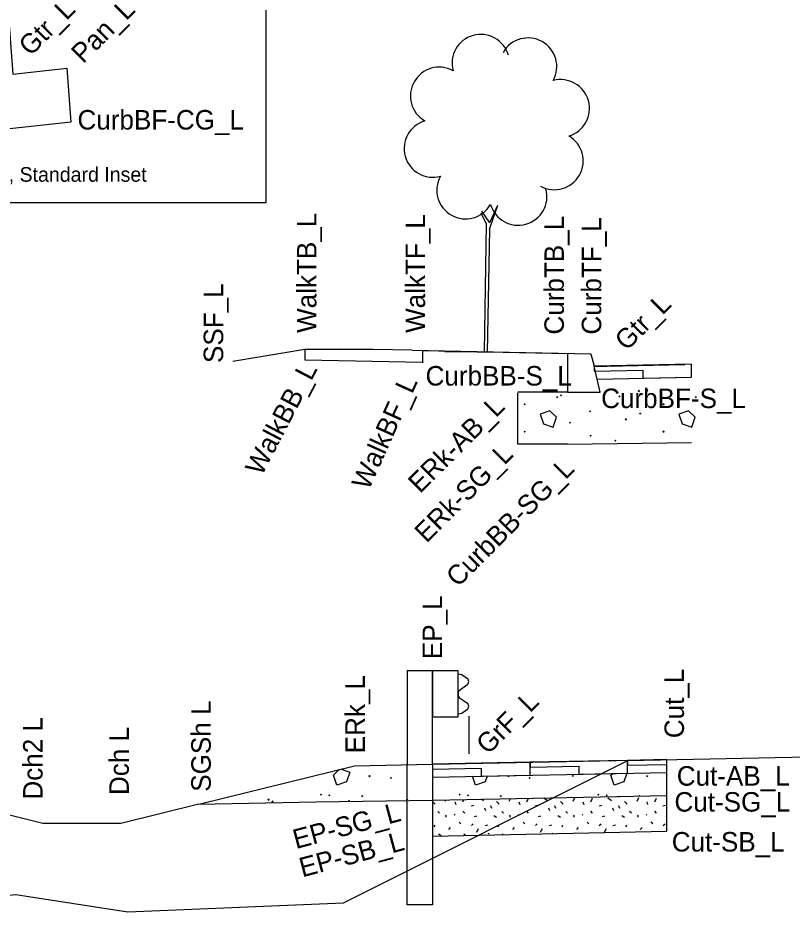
# Model space of a CAD drawing. Extents: x 0 to 1.42, y 0 to 0.92.
# Drawn here: x 0.3094 to 0.6404, y 0.3166 to 0.7008 of the extents above; entities that cross this region are included whole.
import ezdxf

# ---------------------------------------------------------------- set-up
doc = ezdxf.new("R2010")
doc.units = 0
for name, color, linetype in [('E_LDSC_VEG_Deciduous', 7, 'Continuous'), ('Level 14', 7, 'Continuous'), ('Level 63', 7, 'Continuous'), ('P_RDWY_PLAN_Detail', 7, 'Continuous'), ('P_RDWY_PLAN_DetailTx', 7, 'Continuous'), ('S_PROP_ROW', 7, 'Continuous')]:
    doc.layers.add(name, color=color, linetype=linetype)

msp = doc.modelspace()

# ---------------------------------------------------------------- linework, layer by layer
at = {"layer": 'E_LDSC_VEG_Deciduous'}
for centre, radius, start, end in [((0.5072960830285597, 0.6814221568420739), 0.012303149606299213, 16.313852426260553, 195.03894938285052), ((0.5274965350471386, 0.6799151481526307), 0.012303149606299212, 331.3138524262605, 150.03894938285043), ((0.4895086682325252, 0.667436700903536), 0.012303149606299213, 61.31385242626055, 240.03894938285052), ((0.5414819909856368, 0.6621277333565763), 0.012303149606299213, 286.3138524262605, 105.03894938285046), ((0.4868202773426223, 0.6449698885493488), 0.012303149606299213, 106.31385242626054, 285.0389493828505), ((0.5387936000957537, 0.639660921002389), 0.012303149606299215, 241.31385242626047, 60.03894938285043), ((0.5008057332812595, 0.6271824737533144), 0.01230314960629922, 151.31385242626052, 330.0389493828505), ((0.5232725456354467, 0.6244940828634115), 0.012303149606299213, 196.31385242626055, 15.038949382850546)]:
    msp.add_arc(centre, radius, start, end, dxfattribs=at)
at = {"layer": 'Level 14'}
for p, q in [((0.4977306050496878, 0.4204527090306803), (0.4991851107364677, 0.4201957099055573)), ((0.4991851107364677, 0.4201957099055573), (0.5013778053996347, 0.41865918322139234)), ((0.4979930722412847, 0.4134262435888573), (0.5013778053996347, 0.41579391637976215)), ((0.4976212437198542, 0.4127044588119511), (0.4976212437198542, 0.41114059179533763)), ((0.4979930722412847, 0.4104188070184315), (0.5013778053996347, 0.40805113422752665)), ((0.4977306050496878, 0.4033923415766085), (0.4991851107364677, 0.40364934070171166)), ((0.4991851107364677, 0.40364934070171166), (0.5013778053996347, 0.40518586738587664))]:
    msp.add_line(p, q, dxfattribs=at)
for points in [[(0.4866851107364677, 0.3818481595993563), (0.4866851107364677, 0.4217650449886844), (0.47574897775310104, 0.4217650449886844), (0.47574897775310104, 0.3818481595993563)], [(0.4866851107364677, 0.3818481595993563), (0.4866851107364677, 0.3216994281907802), (0.47574897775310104, 0.3216994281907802), (0.47574897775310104, 0.3818481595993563)]]:
    msp.add_lwpolyline(points, dxfattribs=at)
msp.add_lwpolyline([(0.4976212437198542, 0.4217650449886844), (0.4866851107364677, 0.4217650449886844), (0.4866851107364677, 0.4020800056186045), (0.4976212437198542, 0.4020800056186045)], close=True, dxfattribs=at)
for centre, radius, start, end in [((0.5003762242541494, 0.41722560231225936), 0.0017497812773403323, 304.9992805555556, 55.00071666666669), ((0.4984960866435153, 0.41270705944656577), 0.0008748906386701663, 125.01187222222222, 180), ((0.4984960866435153, 0.4111379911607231), 0.0008748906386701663, 180, 234.98812777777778), ((0.5003762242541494, 0.4066194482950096), 0.0017497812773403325, 304.9992833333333, 55.00071944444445)]:
    msp.add_arc(centre, radius, start, end, dxfattribs=at)
at = {"layer": 'Level 63'}
msp.add_lwpolyline([(0.41534290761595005, 0.6217266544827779), (0.2093492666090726, 0.6217266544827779), (0.2093492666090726, 0.7221789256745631), (0.41534290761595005, 0.7221789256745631)], close=True, dxfattribs=at)
at = {"layer": 'P_RDWY_PLAN_Detail'}
for p, q in [((0.5143879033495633, 0.6206599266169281), (0.5109247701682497, 0.6104224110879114)), ((0.5143879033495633, 0.6206599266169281), (0.5109945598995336, 0.613146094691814)), ((0.507298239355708, 0.6175089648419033), (0.5096245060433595, 0.6128309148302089)), ((0.5076012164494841, 0.6182361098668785), (0.5109945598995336, 0.613146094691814)), ((0.5096245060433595, 0.6128309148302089), (0.5087280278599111, 0.558145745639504)), ((0.510951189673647, 0.6105005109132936), (0.5100902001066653, 0.5579801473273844)), ((0.48256132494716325, 0.5533570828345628), (0.48256132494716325, 0.5583822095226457)), ((0.4918710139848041, 0.5581643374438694), (0.5195385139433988, 0.5578846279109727)), ((0.578683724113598, 0.541876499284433), (0.5782191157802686, 0.5414118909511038)), ((0.5782191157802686, 0.541876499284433), (0.578683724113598, 0.5414118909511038)), ((0.5443556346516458, 0.5408064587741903), (0.5231866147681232, 0.5408932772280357)), ((0.5231866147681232, 0.5186843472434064), (0.5231866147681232, 0.5405687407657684)), ((0.5401213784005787, 0.5389331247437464), (0.5396567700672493, 0.5384685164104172)), ((0.5396567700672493, 0.5389331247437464), (0.5401213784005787, 0.5384685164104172)), ((0.5418249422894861, 0.5397083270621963), (0.5413603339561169, 0.5392437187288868)), ((0.5413603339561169, 0.5397083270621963), (0.5418249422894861, 0.5392437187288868)), ((0.5611830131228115, 0.5412570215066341), (0.560719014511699, 0.5407924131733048)), ((0.560719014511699, 0.5412570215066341), (0.5611830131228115, 0.5407924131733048)), ((0.5667583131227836, 0.5392428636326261), (0.5662937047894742, 0.5387782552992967)), ((0.5662937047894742, 0.5392428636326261), (0.5667583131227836, 0.5387782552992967)), ((0.5751212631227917, 0.5415667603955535), (0.5746566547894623, 0.5411021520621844)), ((0.5746566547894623, 0.5415667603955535), (0.5751212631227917, 0.5411021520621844)), ((0.5994362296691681, 0.5389331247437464), (0.5989716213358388, 0.5384685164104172)), ((0.5989716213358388, 0.5389331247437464), (0.5994362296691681, 0.5384685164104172)), ((0.5263379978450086, 0.5358357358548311), (0.5258733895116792, 0.5353711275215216)), ((0.5258733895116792, 0.5358357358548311), (0.5263379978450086, 0.5353711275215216)), ((0.585652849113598, 0.5358357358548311), (0.5851882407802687, 0.5353711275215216)), ((0.5851882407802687, 0.5358357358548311), (0.585652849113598, 0.5353711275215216)), ((0.5542144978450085, 0.5328932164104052), (0.553749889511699, 0.5324286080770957)), ((0.553749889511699, 0.5328932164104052), (0.5542144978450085, 0.5324286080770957)), ((0.5755863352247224, 0.5319639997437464), (0.5751217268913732, 0.5314993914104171)), ((0.5751217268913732, 0.5319639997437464), (0.5755863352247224, 0.5314993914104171)), ((0.5456966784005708, 0.528092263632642), (0.5452320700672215, 0.5276276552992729)), ((0.5452320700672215, 0.528092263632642), (0.5456966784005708, 0.5276276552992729)), ((0.5695459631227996, 0.5294860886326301), (0.5690813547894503, 0.5290214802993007)), ((0.5690813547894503, 0.5294860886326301), (0.5695459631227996, 0.5290214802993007)), ((0.5263379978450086, 0.5242205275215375), (0.5258733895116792, 0.5237559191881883)), ((0.5258733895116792, 0.5242205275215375), (0.5263379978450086, 0.5237559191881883)), ((0.5545242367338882, 0.5225169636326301), (0.5540596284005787, 0.5220523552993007)), ((0.5540596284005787, 0.5225169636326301), (0.5545242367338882, 0.5220523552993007)), ((0.585652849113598, 0.5242205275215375), (0.5851882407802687, 0.5237559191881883)), ((0.5851882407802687, 0.5242205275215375), (0.585652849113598, 0.5237559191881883)), ((0.5443556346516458, 0.5185975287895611), (0.5231866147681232, 0.5186843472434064)), ((0.565054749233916, 0.5203487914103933), (0.5645901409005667, 0.5198841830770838)), ((0.5645901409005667, 0.5203487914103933), (0.565054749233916, 0.5198841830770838)), ((0.5021260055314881, 0.40245278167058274), (0.5021260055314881, 0.38632364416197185)), ((0.4594806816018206, 0.37697243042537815), (0.45994528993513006, 0.37650782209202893)), ((0.45994528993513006, 0.37697243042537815), (0.4594806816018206, 0.37650782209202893)), ((0.5187955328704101, 0.37697243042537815), (0.5192601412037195, 0.37650782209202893)), ((0.5192601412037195, 0.37697243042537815), (0.5187955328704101, 0.37650782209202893)), ((0.5463622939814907, 0.37712729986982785), (0.5468269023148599, 0.37666269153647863)), ((0.5468269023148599, 0.37712729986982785), (0.5463622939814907, 0.37666269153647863)), ((0.5781103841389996, 0.37697243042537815), (0.5785749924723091, 0.37650782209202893)), ((0.5785749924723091, 0.37697243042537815), (0.5781103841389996, 0.37650782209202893)), ((0.46861797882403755, 0.3761980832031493), (0.46908258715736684, 0.3757334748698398)), ((0.46908258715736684, 0.3761980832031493), (0.46861797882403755, 0.3757334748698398)), ((0.527932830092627, 0.3761980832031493), (0.5283974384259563, 0.3757334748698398)), ((0.5283974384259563, 0.3761980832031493), (0.527932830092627, 0.3757334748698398)), ((0.43872832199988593, 0.36907408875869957), (0.4391929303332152, 0.36860948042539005)), ((0.4391929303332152, 0.36907408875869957), (0.43872832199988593, 0.36860948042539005)), ((0.49804317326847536, 0.36907408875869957), (0.49850778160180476, 0.36860948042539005)), ((0.49850778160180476, 0.36907408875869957), (0.49804317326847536, 0.36860948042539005)), ((0.5573580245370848, 0.36907408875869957), (0.5578226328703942, 0.36860948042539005)), ((0.5578226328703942, 0.36907408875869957), (0.5573580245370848, 0.36860948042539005)), ((0.39135542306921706, 0.3659923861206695), (0.39133888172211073, 0.3659758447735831)), ((0.3917020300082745, 0.36607730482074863), (0.3918034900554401, 0.3659758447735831)), ((0.4162722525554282, 0.36690591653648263), (0.4167368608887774, 0.3664413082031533)), ((0.4167368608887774, 0.36690591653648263), (0.4162722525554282, 0.3664413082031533)), ((0.4179758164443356, 0.3661307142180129), (0.4184404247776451, 0.36566610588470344)), ((0.4184404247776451, 0.3661307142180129), (0.4179758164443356, 0.36566610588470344)), ((0.4422907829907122, 0.36876434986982), (0.44275539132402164, 0.3682997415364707)), ((0.44275539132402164, 0.36876434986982), (0.4422907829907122, 0.3682997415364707)), ((0.4506537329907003, 0.3664404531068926), (0.45106603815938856, 0.36602814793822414)), ((0.45111834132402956, 0.3664404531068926), (0.4506993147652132, 0.366021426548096)), ((0.4562290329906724, 0.36845461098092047), (0.4566930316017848, 0.3679900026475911)), ((0.4566930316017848, 0.36845461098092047), (0.4562290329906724, 0.3679900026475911)), ((0.4755871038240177, 0.36690591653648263), (0.47600773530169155, 0.36648528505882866)), ((0.4760517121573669, 0.36690591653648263), (0.47562404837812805, 0.3664782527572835)), ((0.5016056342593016, 0.36876434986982), (0.5020702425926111, 0.3682997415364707)), ((0.5020702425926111, 0.36876434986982), (0.5016056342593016, 0.3682997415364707)), ((0.5155438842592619, 0.36845461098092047), (0.5160078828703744, 0.3679900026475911)), ((0.5160078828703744, 0.36845461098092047), (0.5155438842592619, 0.3679900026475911)), ((0.5609204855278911, 0.36876434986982), (0.5613850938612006, 0.3682997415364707)), ((0.5613850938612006, 0.36876434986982), (0.5609204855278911, 0.3682997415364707)), ((0.5748587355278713, 0.36845461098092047), (0.5750132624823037, 0.3682998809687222)), ((0.5753227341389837, 0.36845461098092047), (0.5751710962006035, 0.3683027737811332))]:
    msp.add_line(p, q, dxfattribs=at)
for points in [[(0.2965892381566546, 0.6999072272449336), (0.3054267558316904, 0.6996089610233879), (0.3071230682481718, 0.6767087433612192), (0.33023510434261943, 0.6793088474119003), (0.33193930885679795, 0.6563020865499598), (0.2965892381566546, 0.6523252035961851)], [(0.5974048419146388, 0.5528064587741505), (0.555738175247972, 0.5519731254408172), (0.555738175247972, 0.5498889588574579), (0.5765715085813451, 0.5503056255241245), (0.5765715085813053, 0.5468897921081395), (0.5974048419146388, 0.5473064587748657)], [(0.5382629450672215, 0.5259240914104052), (0.5396567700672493, 0.530105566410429), (0.5368691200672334, 0.5328932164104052), (0.5326876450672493, 0.5314993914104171), (0.5340814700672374, 0.5273179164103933)], [(0.597577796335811, 0.5259240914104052), (0.5989716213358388, 0.530105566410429), (0.5961839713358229, 0.5328932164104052), (0.5920024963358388, 0.5314993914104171), (0.5933963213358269, 0.5273179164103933)], [(0.5283517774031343, 0.38268149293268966), (0.4866851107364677, 0.3818481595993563), (0.4866851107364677, 0.37976399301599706), (0.5075184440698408, 0.38018065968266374), (0.5075184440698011, 0.3767648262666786), (0.5283517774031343, 0.3771814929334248)], [(0.5700184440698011, 0.38351482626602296), (0.5283517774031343, 0.38268149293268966), (0.5283517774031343, 0.3805973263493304), (0.5491851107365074, 0.38101399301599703), (0.5491851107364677, 0.377598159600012), (0.5700184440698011, 0.37801482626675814)], [(0.5868895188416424, 0.3838522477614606), (0.5700184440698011, 0.38351482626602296), (0.5700184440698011, 0.38143065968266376), (0.5868895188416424, 0.38176808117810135)]]:
    msp.add_lwpolyline(points, close=True, dxfattribs=at)
for points in [[(0.4320959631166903, 0.5591381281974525), (0.40128841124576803, 0.554003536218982)], [(0.4779880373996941, 0.5588047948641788), (0.4613213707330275, 0.5591381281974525), (0.4320061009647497, 0.5591381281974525)], [(0.4320959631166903, 0.5591381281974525), (0.4320061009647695, 0.5546450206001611), (0.48256132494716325, 0.5536339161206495)], [(0.4506020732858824, 0.5591113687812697), (0.447226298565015, 0.5591788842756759)], [(0.4779880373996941, 0.5588047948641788), (0.5544048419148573, 0.5571664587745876), (0.555738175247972, 0.5519731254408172), (0.5612381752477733, 0.5519731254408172), (0.5945715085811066, 0.5526397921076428)], [(0.48256132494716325, 0.558706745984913), (0.5443556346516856, 0.5573819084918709)], [(0.5443556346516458, 0.5573819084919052), (0.5443556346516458, 0.5408064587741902), (0.5583892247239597, 0.5408064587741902), (0.555738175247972, 0.5519731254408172)], [(0.5571711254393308, 0.5463917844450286), (0.5974048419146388, 0.5473064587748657)], [(0.5443556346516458, 0.5185975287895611), (0.5974048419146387, 0.5193464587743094)], [(0.08341356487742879, 0.3083502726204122), (0.09362096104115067, 0.31286508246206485), (0.14012781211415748, 0.3246763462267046), (0.18146723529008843, 0.3268909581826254), (0.2102571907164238, 0.31877071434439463), (0.2715281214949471, 0.32246173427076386), (0.3084383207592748, 0.3261527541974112), (0.35642157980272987, 0.31877071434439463), (0.44858000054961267, 0.3226958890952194), (0.5702261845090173, 0.38351898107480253), (0.6613119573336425, 0.3853406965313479)], [(0.38668511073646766, 0.3648481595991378), (0.4366851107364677, 0.3658481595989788), (0.4868895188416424, 0.36651755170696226), (0.5868895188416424, 0.3685175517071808), (0.5868895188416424, 0.38385224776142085)], [(0.38668511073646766, 0.3648481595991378), (0.4533517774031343, 0.3811814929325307), (0.4866851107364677, 0.3818481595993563), (0.5868895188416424, 0.38385224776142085)], [(0.4475536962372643, 0.3797609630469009), (0.4512732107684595, 0.378521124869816), (0.44987938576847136, 0.374339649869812), (0.44569791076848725, 0.37294582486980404), (0.4443040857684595, 0.37712729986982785), (0.4467378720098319, 0.3795610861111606)], [(0.4866851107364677, 0.37634815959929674), (0.5868895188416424, 0.37835224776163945)], [(0.5100193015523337, 0.37681484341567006), (0.5091942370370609, 0.374339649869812), (0.5050127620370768, 0.37294582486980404), (0.503764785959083, 0.37668975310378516)], [(0.5697322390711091, 0.37800910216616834), (0.5685090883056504, 0.374339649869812), (0.5643276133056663, 0.37294582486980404), (0.5629337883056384, 0.37712729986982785), (0.563694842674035, 0.3778883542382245)], [(0.38668511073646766, 0.3648481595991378), (0.3533517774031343, 0.35651482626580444), (0.320018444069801, 0.35651482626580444), (0.2533517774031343, 0.3731814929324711), (0.23668511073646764, 0.3731814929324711), (0.13962045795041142, 0.324649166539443)], [(0.4866851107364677, 0.35117876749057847), (0.5868895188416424, 0.353182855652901), (0.5868895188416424, 0.36851755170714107)]]:
    msp.add_lwpolyline(points, dxfattribs=at)
at = {"layer": 'S_PROP_ROW'}
for p, q in [((0.48687822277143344, 0.36566989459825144), (0.4877934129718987, 0.36475407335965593)), ((0.4920697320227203, 0.3660712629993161), (0.49234739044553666, 0.3666267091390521)), ((0.49621265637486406, 0.3658552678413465), (0.49659856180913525, 0.36469659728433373)), ((0.49963364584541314, 0.3658549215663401), (0.5000969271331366, 0.366781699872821)), ((0.5085122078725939, 0.3662402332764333), (0.5075910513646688, 0.3669315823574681)), ((0.514034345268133, 0.36586313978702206), (0.515142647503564, 0.36475407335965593)), ((0.5194189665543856, 0.3660712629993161), (0.5199728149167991, 0.3671792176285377)), ((0.5235618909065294, 0.3658552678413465), (0.5239477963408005, 0.36469659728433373)), ((0.5269828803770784, 0.3658549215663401), (0.527722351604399, 0.3673342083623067)), ((0.5358614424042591, 0.3662402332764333), (0.534317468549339, 0.367399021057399)), ((0.5413835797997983, 0.36586313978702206), (0.5424918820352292, 0.36475407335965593)), ((0.546768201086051, 0.3660712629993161), (0.5475404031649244, 0.36761602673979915)), ((0.5509111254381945, 0.3658552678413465), (0.5512970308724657, 0.36469659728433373)), ((0.5543321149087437, 0.3658549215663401), (0.5551043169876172, 0.36739968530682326)), ((0.5632106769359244, 0.3662402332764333), (0.5616667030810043, 0.367399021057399)), ((0.5666878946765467, 0.36782573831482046), (0.5656897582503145, 0.3680935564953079)), ((0.568731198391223, 0.36586313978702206), (0.569839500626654, 0.36475407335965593)), ((0.5741158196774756, 0.3660712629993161), (0.5748880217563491, 0.36761602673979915)), ((0.5782587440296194, 0.3658552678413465), (0.5786446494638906, 0.36469659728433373)), ((0.5816797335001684, 0.3658549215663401), (0.5824519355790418, 0.36739968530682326)), ((0.4896772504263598, 0.3609064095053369), (0.48890528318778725, 0.3616789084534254)), ((0.5004017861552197, 0.3609976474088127), (0.49962981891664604, 0.3617701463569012)), ((0.5042169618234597, 0.3642013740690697), (0.5031619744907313, 0.3639190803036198)), ((0.5089111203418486, 0.3631974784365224), (0.5092970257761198, 0.36203880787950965)), ((0.5120430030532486, 0.36297159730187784), (0.511657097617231, 0.3641302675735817)), ((0.5170264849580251, 0.3609064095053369), (0.5162545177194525, 0.3616789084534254)), ((0.527751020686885, 0.3609976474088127), (0.5269790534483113, 0.3617701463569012)), ((0.5315661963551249, 0.3642013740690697), (0.5305112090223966, 0.3639190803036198)), ((0.536260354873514, 0.3631974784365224), (0.5366462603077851, 0.36203880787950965)), ((0.5393922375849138, 0.36297159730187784), (0.5390063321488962, 0.3641302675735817)), ((0.5443757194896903, 0.3609064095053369), (0.5436037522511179, 0.3616789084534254)), ((0.5551002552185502, 0.3609976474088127), (0.5543282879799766, 0.3617701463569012)), ((0.5589154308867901, 0.3642013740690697), (0.5578604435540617, 0.3639190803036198)), ((0.5636095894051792, 0.3631974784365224), (0.5639954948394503, 0.36203880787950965)), ((0.5667414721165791, 0.36297159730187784), (0.5663555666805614, 0.3641302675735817)), ((0.571723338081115, 0.3609064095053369), (0.5709513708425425, 0.3616789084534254)), ((0.582447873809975, 0.3609976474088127), (0.5816759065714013, 0.3617701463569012)), ((0.586263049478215, 0.3642013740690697), (0.5852080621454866, 0.3639190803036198)), ((0.49227466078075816, 0.3602904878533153), (0.492556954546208, 0.359235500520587)), ((0.4962710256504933, 0.36014367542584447), (0.49593824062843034, 0.36036568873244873)), ((0.5055033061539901, 0.359653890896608), (0.5044483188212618, 0.3593715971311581)), ((0.5140327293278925, 0.3590300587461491), (0.5128747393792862, 0.3598025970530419)), ((0.5196238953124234, 0.3602904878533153), (0.5199061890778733, 0.359235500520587)), ((0.5236202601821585, 0.36014367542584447), (0.5232874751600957, 0.36036568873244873)), ((0.5328525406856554, 0.359653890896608), (0.5317975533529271, 0.3593715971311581)), ((0.5413819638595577, 0.3590300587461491), (0.5402239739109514, 0.3598025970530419)), ((0.5469731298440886, 0.3602904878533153), (0.5472554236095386, 0.359235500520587)), ((0.5509694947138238, 0.36014367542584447), (0.5506367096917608, 0.36036568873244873)), ((0.5602017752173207, 0.359653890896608), (0.5591467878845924, 0.3593715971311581)), ((0.568731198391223, 0.3590300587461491), (0.5675732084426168, 0.3598025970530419)), ((0.5743207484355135, 0.3602904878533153), (0.5746030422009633, 0.359235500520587)), ((0.5783171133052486, 0.36014367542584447), (0.5779843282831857, 0.36036568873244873)), ((0.5868895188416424, 0.3594773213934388), (0.5864944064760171, 0.3593715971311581)), ((0.4873330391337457, 0.3550422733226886), (0.48771914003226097, 0.3558146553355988)), ((0.49423627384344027, 0.3547842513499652), (0.49346415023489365, 0.3540119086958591)), ((0.4988032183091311, 0.35632787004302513), (0.4980312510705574, 0.35710036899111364)), ((0.5032713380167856, 0.3556702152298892), (0.5040434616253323, 0.35644255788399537)), ((0.5055344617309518, 0.35284212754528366), (0.5063066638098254, 0.3543868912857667)), ((0.5101843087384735, 0.3558653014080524), (0.5091293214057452, 0.3555830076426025)), ((0.5146822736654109, 0.3550422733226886), (0.5150683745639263, 0.3558146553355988)), ((0.5215855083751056, 0.3547842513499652), (0.5208133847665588, 0.3540119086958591)), ((0.5261524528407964, 0.35632787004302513), (0.5253804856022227, 0.35710036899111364)), ((0.5306205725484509, 0.3556702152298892), (0.5313926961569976, 0.35644255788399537)), ((0.5328836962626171, 0.35284212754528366), (0.5336558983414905, 0.3543868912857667)), ((0.5375335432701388, 0.3558653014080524), (0.5364785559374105, 0.3555830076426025)), ((0.5420315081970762, 0.3550422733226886), (0.5424176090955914, 0.3558146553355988)), ((0.5489347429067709, 0.3547842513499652), (0.5481626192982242, 0.3540119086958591)), ((0.5535016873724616, 0.35632787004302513), (0.5527297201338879, 0.35710036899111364)), ((0.5579698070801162, 0.3556702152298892), (0.558741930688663, 0.35644255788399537)), ((0.5602329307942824, 0.35284212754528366), (0.5610051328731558, 0.3543868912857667)), ((0.564882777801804, 0.3558653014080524), (0.5638277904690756, 0.3555830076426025)), ((0.569379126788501, 0.3550422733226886), (0.5697652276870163, 0.3558146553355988)), ((0.5762823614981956, 0.3547842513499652), (0.5755102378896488, 0.3540119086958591)), ((0.5808493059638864, 0.35632787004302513), (0.5800773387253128, 0.35710036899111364)), ((0.5853174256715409, 0.3556702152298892), (0.5860895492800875, 0.35644255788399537)), ((0.49031368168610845, 0.35125133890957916), (0.4892628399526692, 0.35195239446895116)), ((0.5007544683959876, 0.35146015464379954), (0.500018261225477, 0.3519513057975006)), ((0.5108268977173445, 0.35195021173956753), (0.510440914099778, 0.3523364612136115)), ((0.5168668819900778, 0.3517824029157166), (0.5166120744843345, 0.35195239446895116)), ((0.537922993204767, 0.3522035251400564), (0.5377901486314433, 0.3523364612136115))]:
    msp.add_line(p, q, dxfattribs=at)

# ---------------------------------------------------------------- texts
at = {"layer": 'P_RDWY_PLAN_Detail'}
msp.add_text('Curb & Gutter, Standard Inset', height=0.006250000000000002, dxfattribs=at).set_placement((0.25385846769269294, 0.6307640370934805))
at = {"layer": 'P_RDWY_PLAN_DetailTx'}
for s, height, rotation, p in [('Gtr_L', 0.008330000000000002, 44.99999923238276, (0.31474654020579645, 0.6841041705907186)), ('Pan_L', 0.008330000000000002, 44.99999923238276, (0.3372595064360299, 0.6809509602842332)), ('WalkTB_L', 0.008330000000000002, 89.99999846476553, (0.43701739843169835, 0.566170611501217)), ('WalkTF_L', 0.008330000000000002, 89.99999846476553, (0.48349099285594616, 0.566170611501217)), ('CurbTB_L', 0.008330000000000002, 89.99999846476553, (0.5428315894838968, 0.5654591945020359)), ('CurbTF_L', 0.008330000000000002, 89.99999846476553, (0.5587986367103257, 0.5654591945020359)), ('SSF_L', 0.008330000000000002, 89.99999846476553, (0.39713876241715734, 0.5533073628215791)), ('Gtr_L', 0.008330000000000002, 44.99999923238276, (0.5696563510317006, 0.5581490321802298)), ('WalkBB_L', 0.008330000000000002, 62.42986205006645, (0.41358655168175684, 0.5047138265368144)), ('WalkBF_L', 0.008329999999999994, 65.74607950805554, (0.4593664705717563, 0.4985604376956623)), ('ERk-AB_L', 0.008330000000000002, 44.99999923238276, (0.4813243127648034, 0.49727034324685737)), ('ERk-SG_L', 0.008330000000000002, 44.99999923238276, (0.48402586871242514, 0.47609878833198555)), ('CurbBB-SG_L', 0.008330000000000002, 44.99999923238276, (0.4975336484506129, 0.457179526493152)), ('EP_L', 0.008330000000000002, 89.99999846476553, (0.4907477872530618, 0.4267521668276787)), ('ERk_L', 0.008330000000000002, 89.99999846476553, (0.45771315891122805, 0.38652004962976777)), ('Cut_L', 0.008330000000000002, 89.99999846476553, (0.5941791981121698, 0.3929793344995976)), ('SGSh L', 0.008330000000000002, 89.99999846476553, (0.3918284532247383, 0.37009501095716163)), ('GrF_L', 0.008330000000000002, 44.99999923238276, (0.5103821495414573, 0.38560501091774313)), ('Dch2 L', 0.008330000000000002, 89.99999846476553, (0.3199009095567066, 0.3667471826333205)), ('Dch L', 0.008330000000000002, 89.99999846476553, (0.35679349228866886, 0.36868194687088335)), ('EP-SG_L', 0.008330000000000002, 14.999999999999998, (0.4282467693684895, 0.3455731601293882)), ('EP-SB_L', 0.008330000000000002, 14.999999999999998, (0.4309563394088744, 0.33347354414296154))]:
    msp.add_text(s, height=height, rotation=rotation, dxfattribs=at).set_placement(p)
for s, p in [('CurbBF-CG_L', (0.33482898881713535, 0.6530896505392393)), ('CurbBB-S_L', (0.4836881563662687, 0.5436822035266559)), ('CurbBF-S_L', (0.5587668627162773, 0.5340497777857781)), ('Cut-AB_L', (0.5910977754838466, 0.3726993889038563)), ('Cut-SG_L', (0.5901124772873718, 0.3616098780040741)), ('Cut-SB_L', (0.5889542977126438, 0.34454267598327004))]:
    msp.add_text(s, height=0.008330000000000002, dxfattribs=at).set_placement(p)

doc.saveas('drawing.dxf')
